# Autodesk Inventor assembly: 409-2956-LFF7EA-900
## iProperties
Created: 2010-09
Part Number: 409-2956-LFF7EA-900
Document SubType Name: Assembly
Designer: S. Boerckel
Mass: 2.71449e+06 g
Surface Area: 794951 cm^2
Volume: 404621 cm^3
Density: 6.70872 g/cm^3
Description: GENERAL ARRANGEMENT UNIT 298035
Material: ASSEMBLY
SMR: =<MATERIAL>
Author: S. Boerckel
Revision Number: 0
Title: GENERAL ARRANGEMENT UNIT-298035
